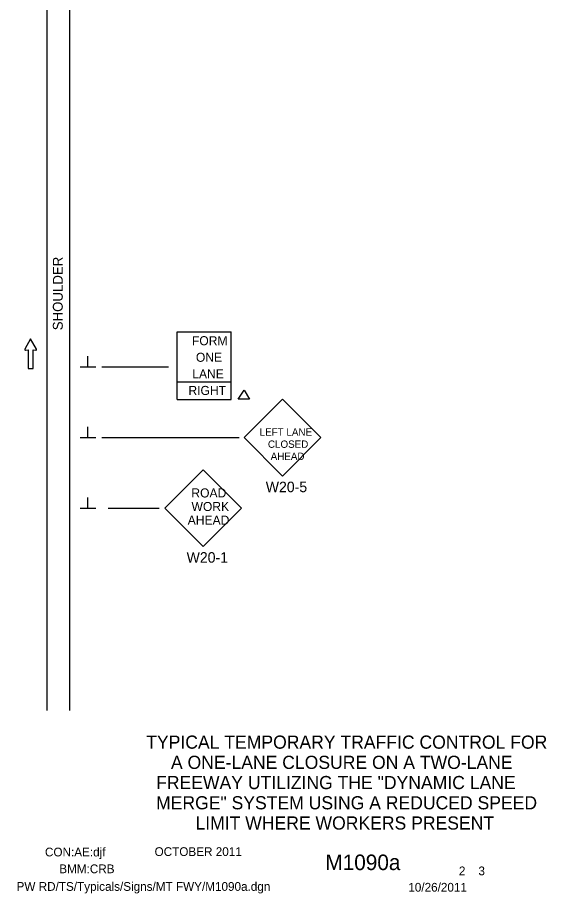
# Model space of a CAD drawing. Extents: x 15278 to 18126, y 1908 to 6555.
# Drawn here: x 16620 to 16994, y 2176 to 2796 of the extents above; entities that cross this region are included whole.
import ezdxf

# ---------------------------------------------------------------- set-up
doc = ezdxf.new("R2010")
doc.units = 0
for name, color, linetype in [('BORDER_SIGNAL_WO', 7, 'Continuous'), ('MT_SCRATCH_LEVEL_E', 7, 'Continuous'), ('PAVT_EDGE_EX', 7, 'Continuous'), ('TRAFFIC_SIGNS_PR', 7, 'Continuous'), ('TYPICAL_TEXT_DIMEN_PR', 7, 'Continuous')]:
    doc.layers.add(name, color=color, linetype=linetype)

msp = doc.modelspace()

# ---------------------------------------------------------------- linework, layer by layer
at = {"layer": 'MT_SCRATCH_LEVEL_E'}
for p, q in [((16628.88, 2568.38), (16624.77, 2561.14)), ((16633.03, 2561.14), (16628.88, 2568.38)), ((16625.25, 2560.45), (16627.03, 2560.77)), ((16627.03, 2560.77), (16627.03, 2547.51)), ((16630.77, 2547.51), (16630.77, 2560.77)), ((16630.77, 2560.77), (16632.55, 2560.45)), ((16627.03, 2547.51), (16630.77, 2547.51))]:
    msp.add_line(p, q, dxfattribs=at)
for centre, start, end in [((16625.17, 2560.91), 150.42484, 279.96381), ((16632.62, 2560.91), 260.03619, 29.77312)]:
    msp.add_arc(centre, 0.463, start, end, dxfattribs=at)
at = {"layer": 'PAVT_EDGE_EX'}
for p, q in [((16640.35, 3138.78), (16640.35, 2305.55)), ((16656.35, 3138.78), (16656.35, 2305.55))]:
    msp.add_line(p, q, dxfattribs=at)
at = {"layer": 'TRAFFIC_SIGNS_PR'}
for p, q in [((16732.58, 2525.54), (16732.58, 2573.5)), ((16732.58, 2573.5), (16770.94, 2573.5)), ((16770.94, 2525.54), (16770.94, 2573.5)), ((16732.58, 2537.95), (16770.94, 2537.95)), ((16732.58, 2525.54), (16770.94, 2525.54)), ((16807.18, 2525.7), (16780.03, 2498.55)), ((16834.33, 2498.55), (16807.18, 2525.7)), ((16780.03, 2498.55), (16807.18, 2471.4)), ((16807.18, 2471.4), (16834.33, 2498.55)), ((16751.15, 2475.85), (16724, 2448.69)), ((16778.3, 2448.69), (16751.15, 2475.85)), ((16724, 2448.69), (16751.15, 2421.54)), ((16751.15, 2421.54), (16778.3, 2448.69))]:
    msp.add_line(p, q, dxfattribs=at)
at = {"layer": 'TYPICAL_TEXT_DIMEN_PR'}
for p, q in [((16669.48, 2548.48), (16669.48, 2556.26)), ((16675.1, 2548.48), (16663.85, 2548.48)), ((16726.53, 2548.48), (16679.35, 2548.48)), ((16669.48, 2498.48), (16669.48, 2506.26)), ((16675.1, 2498.48), (16663.85, 2498.48)), ((16776.53, 2498.48), (16679.35, 2498.48)), ((16669.48, 2448.48), (16669.48, 2456.26)), ((16675.1, 2448.48), (16663.85, 2448.48)), ((16719.83, 2448.48), (16683.78, 2448.48))]:
    msp.add_line(p, q, dxfattribs=at)
msp.add_lwpolyline([(16775.77, 2525.83), (16780.13, 2532.14), (16783.83, 2525.83)], close=True, dxfattribs=at)

# ---------------------------------------------------------------- texts
at = {"layer": 'BORDER_SIGNAL_WO'}
for s, height, p in [('TYPICAL TEMPORARY TRAFFIC CONTROL FOR', 9.3, (16710.73, 2278.54)), ('A ONE-LANE CLOSURE ON A TWO-LANE', 9.3, (16728.24, 2264.24)), ('FREEWAY UTILIZING THE "DYNAMIC LANE', 9.3, (16717.74, 2249.94)), ('MERGE" SYSTEM USING A REDUCED SPEED', 9.3, (16717.7, 2235.64)), ('LIMIT WHERE WORKERS PRESENT', 9.3, (16745.6, 2221.34)), ('CON:AE:djf  ', 6.2, (16639.05, 2202.35)), ('    OCTOBER 2011    ', 6.2, (16707.44, 2202.63)), ('    M1090a   ', 11, (16821.22, 2192.67)), ('BMM:CRB   ', 6.2, (16649.17, 2190.46)), (' 2    3 ', 6.2, (16929.81, 2188.99)), ('PW RD/TS/Typicals/Signs/MT FWY/M1090a.dgn      ', 6.2, (16618.92, 2178)), ('10/26/2011    ', 6.2, (16896.29, 2177.42))]:
    msp.add_text(s, height=height, dxfattribs=at).set_placement(p)
at = {"layer": 'TRAFFIC_SIGNS_PR'}
for s, height, p in [('FORM', 6.394, (16743.11, 2563.91)), ('ONE', 6.394, (16745.92, 2552.19)), ('LANE', 6.394, (16743.34, 2540.47)), ('RIGHT', 6.394, (16740.62, 2528.74)), ('LEFT LANE', 5.2, (16791.06, 2499.94)), ('CLOSED', 5.2, (16796.89, 2491.34)), ('AHEAD', 5.2, (16798.84, 2482.74)), ('W20-5', 7.44, (16795.36, 2459.96)), ('ROAD', 6.4, (16742.69, 2456.23)), ('WORK', 6.4, (16742.8, 2446.63)), ('AHEAD', 6.4, (16740.11, 2437.03)), ('W20-1', 7.44, (16739.32, 2410.1))]:
    msp.add_text(s, height=height, dxfattribs=at).set_placement(p)
at = {"layer": 'TYPICAL_TEXT_DIMEN_PR'}
msp.add_text('SHOULDER', height=7, rotation=90, dxfattribs=at).set_placement((16651.63, 2574.49))

doc.saveas('drawing.dxf')
